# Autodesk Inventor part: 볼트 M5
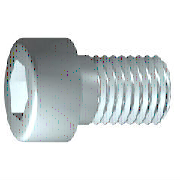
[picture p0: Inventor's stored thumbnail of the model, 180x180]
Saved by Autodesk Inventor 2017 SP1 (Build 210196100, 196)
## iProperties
IsCustomPart: 0
Created: 2021-07
Part Number: 볼트 M5
Material: 강철, 연강
Description: 6각머리 태핑 나사
Document SubType Name: Modeling
Standard: KS B 1003
Standards Organization: KS
Language: ko-KR
Size Designation: M 5 x 20
Categories: <MemberInstance><Categories><Category DisplayName="조임쇠" InternalName="e4da775c-781d-43d5-af7c-5136215cf5a6" Mnemonic="FSTN"><Category DisplayName="볼트" InternalN
Density: 7.86 g/cm^3
Mass: 4.9629 g
Surface Area: 5.88237 cm^2
Volume: 0.631412 cm^3
Project: mdu
Appearance: 강철
Author: mdu
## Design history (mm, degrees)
sketch "스케치1"
  geometry: L1 (-1.167, 0)-(20, 0); L2 (20, 0)-(20, 2.5); L3 (20, 2.5)-(2, 2.5); L4 (2, 2.5)-(1.509, 2.5); L5 (1.509, 2.5)-(0, 2.5); L6 (0, 2.5)-(0, 4.25); L7 (0, 4.25)-(-5, 4.25); L8 (-5, 4.25)-(-5, 2.309); L9 (-5, 2.309)-(-2.5, 2.309); L10 (-2.5, 2.309)-(-1.167, 0); L11 (-10, 0)-(25, 0) reference; L12 (0, -0.85)-(0, 5.1) reference; L13 (2, 2.5)-(0, 2.5)
  constraints: 22 end point, 6 parallel, 2 collinear, 2 perpendicular, 1 horizontal, 1 point on line
  dimensions: "d1" = 18 distance from line of L3.end L2 (= GEL); "d2" = 0.49086 distance of L4.end L3.end (computed from GAL); "d3" = 5 distance between parallel lines of L8 L6 (= KOH); "d4" = 2.5 distance of L8.end L9.end (= INTI); "d5" = 60 deg angle of L10 L1; "d6" = 5 diameter of L3 L1 (= GD); "d7" = 5 diameter of L5 L1 (= BDM); "d8" = 4.6188 diameter of L9 L1 (= 1.1547 x SW); "d9" = 8.5 diameter of L7 L1 (= KOD); "d26" = 20 distance between parallel lines of L12 L2 (= NLG)
revolve "본체" sketch "스케치1" stored, may be unused: angle "d10" = 90 deg
sketch "스케치2"
  geometry: L1 (0, -5.95)-(0, 5.95) reference; L2 (-5.95, 0)-(5.95, 0) reference; L3 (2.309, 0)-(1.155, -2); L4 (1.155, -2)-(-1.155, -2); L5 (-1.155, -2)-(-2.309, 0); L6 (-2.309, 0)-(-1.155, 2); L7 (-1.155, 2)-(1.155, 2); L8 (1.155, 2)-(2.309, 0); 2 further points
  constraints: 12 end point, 1 coincident, 1 horizontal alignment, 1 point on line, 12 other
extrude "슬롯" join sketch "스케치2" stored distance "d11" = 10; taper "d12" = 0 deg
workplane "Work Plane1"
fillet "Fillet2" dims "d30" = 0.1 (= R)
body "Solid1"
fillet "모깎기1" dims "d17" = 0.5 (= RR)
feature "스레드" dims "d13" = 18 (= GEL), "d14" = 0
chamfer "모따기1" distance "d15" = 0.49076 (= -0.5 x SPD + 0.5 x GD); stored, may be unused: second distance "d16" = 0.49076 (= GUL), angle "d27" = 45 deg
other parameters: "GD" = 5 (= NND) [user parameter; used in 2 equation terms], "NLG" = 20 [user parameter; used in 1 equation term], "GEL" = 18 [user parameter; used in 2 equation terms], "KOD" = 8.5 [user parameter; used in 1 equation term], "KOH" = 5 [user parameter; used in 1 equation term], "INTI" = 2.5 [user parameter; used in 1 equation term], "GAL" = 0.49076 (= 0.61345 x PTC) [user parameter; used in 1 equation term], "GUL" = 0.49076 (= 0.61345 x PTC) [user parameter; used in 1 equation term], "BDM" = 5 (= NND) [user parameter; used in 1 equation term], "SW" = 4 [user parameter; used in 2 equation terms], "RR" = 0.5 [user parameter; used in 1 equation term], "SPD" = 4.01848 (= NND - 1.2269 x PTC) [user parameter; used in 1 equation term], "d19" = 0, "d28" = 0, "d29" = 0, "R" = 0.1 [user parameter; used in 1 equation term], "PHH" = 0.2 [user parameter], "GD1" = 4.01848 (= THREADDIA - 1.2269 x PTC) [user parameter], "THREADDIA" = 5 [user parameter; used in 1 equation term], "FAWI" = 45 deg [user parameter], "TPU" = 12.5 (computed from PTC) [user parameter], "PTC" = 0.8 [user parameter; used in 5 equation terms], "NND" = 5 [user parameter; used in 3 equation terms], "TOA" = 30 deg [user parameter], "E0" = 4.62 (= 1.155 x SW) [user parameter]
